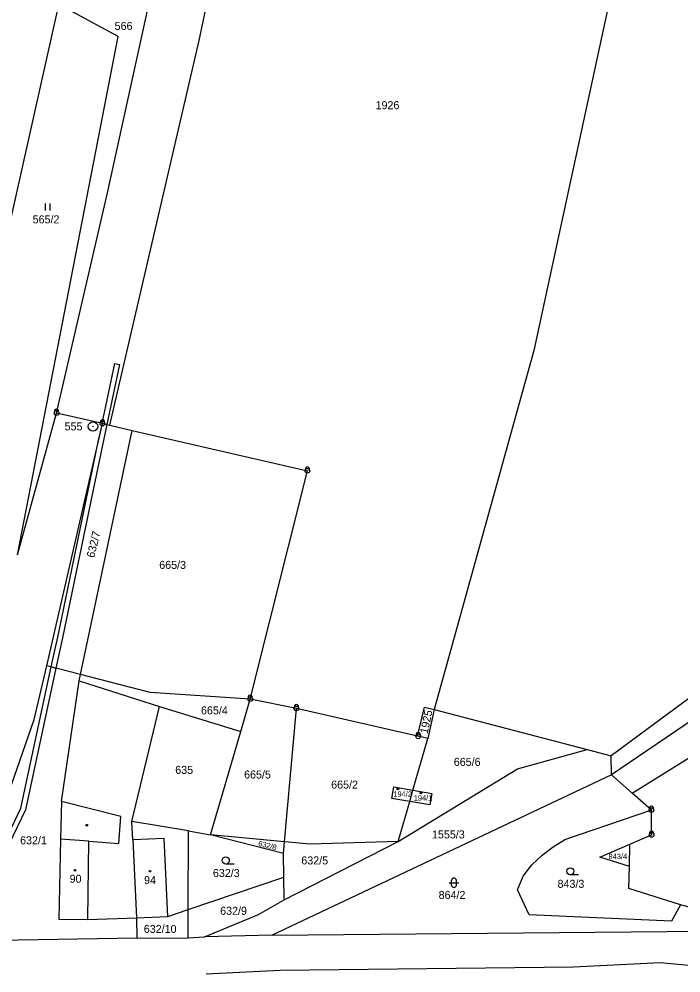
# Model space of a CAD drawing. Extents: x -801826 to -800592, y -1032871 to -1031813.
# Drawn here: x -800970.8 to -800830.2, y -1032380.8 to -1032178.1 of the extents above; entities that cross this region are included whole.
import ezdxf

# ---------------------------------------------------------------- set-up
doc = ezdxf.new("R2010")
doc.units = 0
for name, color, linetype in [('Vrstva 1', 7, 'Continuous'), ('Vrstva 17', 7, 'Continuous'), ('Vrstva 18', 7, 'Continuous'), ('Vrstva 19', 7, 'Continuous'), ('Vrstva 24', 7, 'Continuous'), ('Vrstva 25', 7, 'Continuous'), ('Vrstva 27', 7, 'Continuous'), ('Vrstva 4', 7, 'Continuous')]:
    doc.layers.add(name, color=color, linetype=linetype)

msp = doc.modelspace()

# ---------------------------------------------------------------- linework, layer by layer
at = {"layer": 'Vrstva 1'}
for p, q in [((-800838.07, -1032140.21), (-800861.49, -1032248.55)), ((-800932.6, -1032182.67), (-800928.13, -1032161.88)), ((-800962.57, -1032175.77), (-800982.29, -1032263)), ((-800949.8, -1032181.86), (-800959.49, -1032176.59)), ((-800952.04, -1032215.07), (-800943.39, -1032175.71)), ((-800971.16, -1032291.94), (-800949.8, -1032181.86)), ((-800951.54, -1032264.44), (-800932.6, -1032182.67)), ((-800962.88, -1032261.83), (-800952.04, -1032215.07)), ((-800861.49, -1032248.55), (-800882.68, -1032324.85)), ((-800971.16, -1032291.94), (-800962.88, -1032261.83)), ((-800953.12, -1032264.08), (-800962.88, -1032261.83)), ((-800964.96, -1032315.54), (-800953.12, -1032264.08)), ((-800953.12, -1032264.08), (-800952.21, -1032264.29)), ((-800952.21, -1032264.29), (-800951.54, -1032264.44)), ((-800951.54, -1032264.44), (-800946.79, -1032265.54)), ((-800957.79, -1032317.39), (-800946.79, -1032265.54)), ((-800946.79, -1032265.54), (-800909.58, -1032274.11)), ((-800921.73, -1032322.6), (-800909.58, -1032274.11)), ((-800805.86, -1032305.7), (-800845.05, -1032334.64)), ((-800803.13, -1032310.28), (-800844.97, -1032338.69)), ((-800967.6, -1032326.98), (-800964.96, -1032315.54)), ((-800957.79, -1032317.39), (-800964.96, -1032315.54)), ((-800961.82, -1032344.38), (-800958.08, -1032318.74)), ((-800958.08, -1032318.74), (-800957.79, -1032317.39)), ((-800958.08, -1032318.74), (-800940.99, -1032324.2)), ((-800943.02, -1032321.19), (-800957.79, -1032317.39)), ((-800921.73, -1032322.6), (-800943.02, -1032321.19)), ((-800923.74, -1032329.48), (-800921.73, -1032322.6)), ((-800911.93, -1032324.58), (-800921.73, -1032322.6)), ((-800946.85, -1032348.61), (-800940.99, -1032324.2)), ((-800940.99, -1032324.2), (-800923.74, -1032329.48)), ((-800914.45, -1032352.94), (-800911.93, -1032324.58)), ((-800886.21, -1032330.48), (-800911.93, -1032324.58)), ((-800886.21, -1032330.48), (-800884.71, -1032324.32)), ((-800884.71, -1032324.32), (-800882.68, -1032324.85)), ((-800882.68, -1032324.85), (-800883.98, -1032330.97)), ((-800882.68, -1032324.85), (-800850.14, -1032333.31)), ((-800975.92, -1032350.71), (-800967.6, -1032326.98)), ((-800930.16, -1032351.48), (-800923.74, -1032329.48)), ((-800887.15, -1032341.95), (-800883.98, -1032330.97)), ((-800886.04, -1032330.52), (-800886.21, -1032330.48)), ((-800883.98, -1032330.97), (-800886.04, -1032330.52)), ((-800840.56, -1032342.6), (-800822.19, -1032331.13)), ((-800864.96, -1032337.41), (-800850.14, -1032333.31)), ((-800850.14, -1032333.31), (-800845.05, -1032334.64)), ((-800844.97, -1032338.69), (-800845.05, -1032334.64)), ((-800890.29, -1032352.85), (-800864.96, -1032337.41)), ((-800844.97, -1032338.69), (-800917.05, -1032372.74)), ((-800840.56, -1032342.6), (-800844.97, -1032338.69)), ((-800891.61, -1032343.71), (-800891.19, -1032341.24)), ((-800891.19, -1032341.24), (-800887.15, -1032341.95)), ((-800887.84, -1032344.36), (-800887.15, -1032341.95)), ((-800887.15, -1032341.95), (-800883.16, -1032342.65)), ((-800883.16, -1032342.65), (-800883.58, -1032345.09)), ((-800836.51, -1032346.18), (-800840.56, -1032342.6)), ((-800961.82, -1032344.38), (-800962.01, -1032352.37)), ((-800887.84, -1032344.36), (-800891.61, -1032343.71)), ((-800890.29, -1032352.85), (-800887.84, -1032344.36)), ((-800883.58, -1032345.09), (-800887.84, -1032344.36)), ((-800836.51, -1032346.18), (-800854.96, -1032352.52)), ((-800836.46, -1032351.47), (-800836.51, -1032346.18)), ((-800946.66, -1032352.54), (-800946.85, -1032348.61)), ((-800934.84, -1032350.62), (-800946.85, -1032348.61)), ((-800934.91, -1032367.3), (-800934.84, -1032350.62)), ((-800934.84, -1032350.62), (-800930.16, -1032351.48)), ((-800914.67, -1032355.45), (-800930.16, -1032351.48)), ((-800914.45, -1032352.94), (-800930.16, -1032351.48)), ((-800841.06, -1032353.42), (-800836.46, -1032351.47)), ((-800962.01, -1032352.37), (-800962.4, -1032369.37)), ((-800946.66, -1032352.54), (-800945.92, -1032369.12)), ((-800914.67, -1032355.45), (-800914.45, -1032352.94)), ((-800914.53, -1032365.29), (-800890.29, -1032352.85)), ((-800908.96, -1032353.43), (-800914.45, -1032352.94)), ((-800890.29, -1032352.85), (-800908.96, -1032353.43)), ((-800857.4, -1032354.02), (-800854.96, -1032352.52)), ((-800847.46, -1032356.22), (-800841.06, -1032353.42)), ((-800841.14, -1032358.19), (-800841.06, -1032353.42)), ((-800914.6, -1032360.42), (-800914.67, -1032355.45)), ((-800861.91, -1032357.85), (-800859.72, -1032355.77)), ((-800859.72, -1032355.77), (-800857.4, -1032354.02)), ((-800863.75, -1032360.26), (-800861.91, -1032357.85)), ((-800841.14, -1032358.19), (-800847.46, -1032356.22)), ((-800841.28, -1032362.88), (-800841.14, -1032358.19)), ((-800934.91, -1032367.3), (-800914.6, -1032360.42)), ((-800914.53, -1032365.29), (-800914.6, -1032360.42)), ((-800864.98, -1032363.15), (-800863.75, -1032360.26)), ((-800862.47, -1032368.47), (-800864.98, -1032363.15)), ((-800830.33, -1032366.35), (-800841.28, -1032362.88)), ((-800919.97, -1032368.38), (-800914.53, -1032365.29)), ((-800939.25, -1032368.8), (-800934.91, -1032367.3)), ((-800934.94, -1032373.3), (-800934.91, -1032367.3)), ((-800830.33, -1032366.35), (-800832.2, -1032369.79)), ((-800824.9, -1032367.82), (-800830.33, -1032366.35)), ((-800962.4, -1032369.37), (-800956.25, -1032369.45)), ((-800956.25, -1032369.45), (-800945.92, -1032369.12)), ((-800945.92, -1032369.12), (-800939.25, -1032368.8)), ((-800945.92, -1032369.12), (-800945.84, -1032373.44)), ((-800931.47, -1032373.12), (-800919.97, -1032368.38)), ((-800832.2, -1032369.79), (-800862.47, -1032368.47)), ((-800917.05, -1032372.74), (-800823.7, -1032371.87)), ((-800945.84, -1032373.44), (-800975.27, -1032373.92)), ((-800945.84, -1032373.44), (-800934.94, -1032373.3)), ((-800934.94, -1032373.3), (-800931.47, -1032373.12)), ((-800917.05, -1032372.74), (-800931.47, -1032373.12)), ((-800853.05, -1032379.59), (-800915.4, -1032380.25)), ((-800834.63, -1032378.64), (-800853.05, -1032379.59)), ((-800815.7, -1032380.41), (-800834.63, -1032378.64)), ((-800915.4, -1032380.25), (-800931.09, -1032381.06))]:
    msp.add_line(p, q, dxfattribs=at)
at = {"layer": 'Vrstva 24'}
for centre, radius in [((-800962.88, -1032261.83), 0.5), ((-800962.88, -1032261.83), 0.0364), ((-800955.13, -1032264.67), 1), ((-800955.13, -1032264.67), 0.0439), ((-800953.12, -1032264.08), 0.5), ((-800953.12, -1032264.08), 0.0364), ((-800909.58, -1032274.11), 0.5), ((-800909.58, -1032274.11), 0.0364), ((-800921.73, -1032322.6), 0.5), ((-800921.73, -1032322.6), 0.0364), ((-800911.93, -1032324.58), 0.5), ((-800911.93, -1032324.58), 0.0364), ((-800886.04, -1032330.52), 0.5), ((-800886.04, -1032330.52), 0.0364), ((-800836.51, -1032346.18), 0.5), ((-800836.51, -1032346.18), 0.0364), ((-800836.46, -1032351.47), 0.5), ((-800836.46, -1032351.47), 0.0364)]:
    msp.add_circle(centre, radius, dxfattribs=at)
for centre in [(-800962.88, -1032261.46), (-800953.12, -1032263.71), (-800909.58, -1032273.74), (-800921.73, -1032322.23), (-800911.93, -1032324.21), (-800886.04, -1032330.15), (-800836.51, -1032345.81), (-800836.46, -1032351.1)]:
    msp.add_arc(centre, 0.45, 344.4473, 196.3778, dxfattribs=at)
at = {"layer": 'Vrstva 25'}
for p, q in [((-800965.26, -1032217.3), (-800965.26, -1032218.8)), ((-800964.23, -1032218.8), (-800964.23, -1032217.3)), ((-800925.17, -1032357.65), (-800926.92, -1032357.65)), ((-800879.44, -1032361.63), (-800877.44, -1032361.63)), ((-800878.94, -1032362.13), (-800878.94, -1032361.13)), ((-800877.94, -1032362.13), (-800877.94, -1032361.13)), ((-800851.98, -1032359.95), (-800853.73, -1032359.95))]:
    msp.add_line(p, q, dxfattribs=at)
for centre, radius in [((-800890.38, -1032341.73), 0.175), ((-800885.47, -1032342.55), 0.175), ((-800956.45, -1032349.4), 0.175), ((-800926.92, -1032356.9), 0.75), ((-800958.95, -1032358.97), 0.175), ((-800943.02, -1032359.17), 0.175), ((-800853.73, -1032359.2), 0.75)]:
    msp.add_circle(centre, radius, dxfattribs=at)
for centre, start, end in [((-800878.44, -1032361.13), 0, 180), ((-800878.44, -1032362.13), 180, 0)]:
    msp.add_arc(centre, 0.5, start, end, dxfattribs=at)
at = {"layer": 'Vrstva 27'}
for points in [[(-800953.19, -1032264.06), (-800950.51, -1032251.29), (-800949.53, -1032251.49), (-800952.21, -1032264.29), (-800953.12, -1032264.08), (-800953.19, -1032264.06)], [(-800963.99, -1032315.79), (-800962.62, -1032309.42), (-800955.74, -1032276.26), (-800953.93, -1032267.6), (-800953.12, -1032264.08), (-800952.21, -1032264.29), (-800954.76, -1032276.46), (-800961.64, -1032309.62), (-800963.02, -1032316.04), (-800963.99, -1032315.79)], [(-800970.45, -1032345.79), (-800963.99, -1032315.79), (-800963.02, -1032316.04), (-800969.49, -1032346.11), (-800977.45, -1032362.66), (-800977.05, -1032359.51), (-800970.45, -1032345.79)]]:
    msp.add_lwpolyline(points, dxfattribs=at)
at = {"layer": 'Vrstva 4'}
for p, q in [((-800949.21, -1032347.53), (-800961.82, -1032344.38)), ((-800949.65, -1032353.31), (-800949.21, -1032347.53)), ((-800956.03, -1032352.82), (-800962.01, -1032352.37)), ((-800956.25, -1032369.45), (-800956.03, -1032352.82)), ((-800956.03, -1032352.82), (-800949.65, -1032353.31)), ((-800939.98, -1032352.22), (-800946.66, -1032352.54)), ((-800939.25, -1032368.8), (-800939.98, -1032352.22))]:
    msp.add_line(p, q, dxfattribs=at)

# ---------------------------------------------------------------- texts
at = {"layer": 'Vrstva 17'}
msp.add_text('555', height=1.7, dxfattribs=at).set_placement((-800961.17, -1032265.52))
at = {"layer": 'Vrstva 18'}
for s, height, p in [('566', 1.7, (-800950.53, -1032180.44)), ('1926', 1.7, (-800895.1, -1032197.28)), ('565/2', 1.7, (-800967.95, -1032221.54)), ('665/3', 1.7, (-800941.06, -1032294.95)), ('665/4', 1.7, (-800932.19, -1032325.86)), ('665/6', 1.7, (-800878.48, -1032336.8)), ('635', 1.7, (-800937.66, -1032338.5)), ('665/5', 1.7, (-800923.03, -1032339.49)), ('665/2', 1.7, (-800904.53, -1032341.63)), ('632/1', 1.7, (-800970.62, -1032353.46)), ('1555/3', 1.7, (-800883.11, -1032352.21)), ('843/4', 1.14, (-800845.6, -1032356.61)), ('632/5', 1.7, (-800910.87, -1032357.74)), ('632/3', 1.7, (-800929.66, -1032360.41)), ('843/3', 1.7, (-800856.44, -1032362.71)), ('864/2', 1.7, (-800881.7, -1032365.07)), ('632/9', 1.7, (-800928.12, -1032368.44)), ('632/10', 1.7, (-800944.34, -1032372.29))]:
    msp.add_text(s, height=height, dxfattribs=at).set_placement(p)
for s, height, rotation, p in [('632/7', 1.7, 76.3496, (-800954.88, -1032292.69)), ('1925', 1.7, 78.0368, (-800884.04, -1032330.08)), ('632/8', 1.14, 346.1153, (-800920.12, -1032353.77))]:
    msp.add_text(s, height=height, rotation=rotation, dxfattribs=at).set_placement(p)
at = {"layer": 'Vrstva 19'}
for s, height, p in [('194/2', 1.14, (-800891.32, -1032343.35)), ('194/1', 1.14, (-800886.99, -1032344.17)), ('90', 1.7, (-800960.09, -1032361.63)), ('94', 1.7, (-800944.29, -1032361.92))]:
    msp.add_text(s, height=height, dxfattribs=at).set_placement(p)

doc.saveas('drawing.dxf')
